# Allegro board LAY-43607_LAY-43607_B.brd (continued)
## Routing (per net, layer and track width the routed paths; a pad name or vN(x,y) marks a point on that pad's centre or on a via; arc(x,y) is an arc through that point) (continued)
CPU_RESET_REQ_B: length 88.3
  TOP w0.137: v3(71.83,49.39) 71.43,49 U14.F10 ; v2(127.13,40.21) 128.21,40.21 129.8,41.8 129.8,43.21 130.44,43.86 J14.2
  L3_INT_1 w0.107: v2(115.3,32.02) 114.5,32.82 114.5,43.92 105.39,53.03 104.4,53.03 102.57,54.86 96.08,54.86 95.16,53.95 87.37,53.95 86.43,54.88 84.48,54.88 82.15,52.56 82.15,51.11 v2(82.51,50.76)
  BOTTOM w0.137: v2(115.3,32.02) 122.99,32.02 127.13,36.16 v2(127.13,40.21) ; v2(82.51,50.76) 82.12,50.37 77.26,50.37 75.91,49.02 72.2,49.02 v3(71.83,49.39)
CPU_SPI_PCS0: length 58.9
  TOP w0.137: v2(63.18,72.87) 59.88,69.57 59.88,66.76 59.94,66.69 59.94,59.19 62.05,57.08 62.11,57.08 62.62,56.57 U14.U1 ; U36.6 82.29,96.74 82.27,96.73 v2(82.27,96.3)
  L3_INT_1 w0.107: v2(63.18,72.87) 63.18,73.28 63.23,73.34 63.23,74.39 65.37,76.53 69.63,76.53 70.25,77.15 72.84,77.15 73.98,78.29 73.98,86.81 75.27,88.1 75.27,89.51 79.63,93.87 79.63,94.02 79.35,94.3 79.35,94.45 79.5,94.6 79.65,94.6 79.93,94.32 80.08,94.32 80.23,94.47 80.23,94.62 79.95,94.9 79.95,95.05 80.1,95.2 80.26,95.2 80.53,94.93 80.68,94.93 81.77,96.01 81.98,96.01 v2(82.27,96.3)
  BOTTOM w0.137: R861.2 82.15,96.49 82.27,96.36 v2(82.27,96.3)
CPU_SPI_PCS1: length 58.7
  TOP w0.137: v2(82.98,96.37) 82.92,96.43 82.92,96.56 82.79,96.69 82.79,96.77 82.78,96.78 U36.7 ; v2(64.52,72.84) 64.52,71.47 63.71,70.66 63.71,69.34 63.57,69.21 63.57,59.08 64.58,58.07 64.58,54.96 U14.R3
  L3_INT_1 w0.107: v2(82.98,96.37) 82.98,95.33 82.37,94.72 82.22,94.72 82.06,94.88 81.91,94.88 81.76,94.73 81.76,94.58 81.92,94.42 81.92,94.27 78,90.35 78,82.49 74.76,79.26 74.76,78.49 71.78,75.5 68.67,75.5 68.14,76.03 65.32,76.03 63.54,74.26 63.54,73.24 63.95,72.84 v2(64.52,72.84)
  BOTTOM w0.137: v2(82.98,96.37) 83.09,96.49 R862.2
CPU_SPI_PCS2: length 60.6
  TOP w0.137: U540.7 85.78,96.8 85.95,96.63 85.95,96.45 v2(86.02,96.38) ; U14.T3 62.98,55.03 62.98,56.63 61.25,58.36 61.25,62.08 60.34,62.99 60.34,66.92 60.24,67.02 60.24,69.37 63.22,72.35 v2(64,72.35)
  L3_INT_1 w0.107: v2(64,72.35) 65.13,72.35 65.89,73.1 71.72,73.1 79.42,80.8 79.42,81.84 82.76,85.18 82.76,92.25 86.01,95.5 86.01,95.97 86.02,95.97 v2(86.02,96.38)
  BOTTOM w0.137: R860.2 86.22,96.66 86.02,96.47 v2(86.02,96.38)
CPU_SPI_PCS3: length 58.4
  TOP w0.137: U14.V1 61.82,56.2 v2(61.42,56.6) ; U540.6 85.28,96.61 85.31,96.58 v2(85.31,96.46)
  L3_INT_1 w0.107: v2(63.97,73.43) 65.38,73.43 65.9,73.95 70.74,73.95 75.15,78.36 75.15,79.2 80.2,84.25 80.2,91.14 83.21,94.15 83.21,94.33 83.09,94.44 83.09,94.62 83.22,94.75 83.39,94.75 83.51,94.63 83.69,94.63 83.81,94.75 83.81,94.93 83.7,95.05 83.7,95.22 83.82,95.35 84,95.35 84.11,95.23 84.29,95.23 84.89,95.84 84.89,96.05 v2(85.31,96.46)
  BOTTOM w0.137: v2(63.97,73.43) 63.67,73.13 63.67,72.74 60.16,69.22 60.16,64.11 61.34,62.93 61.34,61.93 61.82,61.44 61.82,57.39 61.42,56.99 v2(61.42,56.6) ; R859.2 85.19,96.59 v2(85.31,96.46)
CPU_SPI_SCK: length 58.9
  TOP w0.137: U14.U2 62.22,55.8 62.22,56.36 59.6,58.98 59.6,66.38 59.37,66.61 59.37,69.76 v2(62.37,72.76) ; U539.7 79.69,96.81 v2(79.41,96.54) 79.19,96.76 U539.6
  L3_INT_1 w0.107: v2(62.37,72.76) 62.37,73.97 65.25,76.84 67.1,76.84 72.25,81.98 72.25,82.59 72.99,83.34 72.99,90.12 76.72,93.85 76.72,94 76.23,94.49 76.23,94.64 76.38,94.8 76.53,94.8 77.02,94.3 77.18,94.3 77.33,94.45 77.33,94.6 76.83,95.1 76.83,95.25 76.98,95.4 77.13,95.4 77.63,94.91 77.78,94.91 77.93,95.06 77.93,95.21 77.44,95.7 77.44,95.85 77.59,96 77.74,96 78.23,95.51 78.38,95.51 v2(79.41,96.54)
CPU_SPI_SIN: length 55.1
  TOP w0.137: v2(62.22,55) U14.U3 ; v2(76.19,96.33) 76.19,96.76 76.19,96.76 U37.2
  L3_INT_1 w0.107: v2(76.19,96.33) 74.81,94.96 74.66,94.96 74.45,95.16 74.29,95.16 74.15,95.02 74.15,94.87 74.36,94.66 74.36,94.51 74.21,94.35 74.05,94.35 73.87,94.54 73.71,94.54 73.56,94.39 73.56,94.24 73.75,94.05 73.75,93.9 70.24,90.39 70.24,85.77 70.4,85.62 70.4,83.57 69.78,82.95 69.78,79.98 68.14,78.34 65.08,78.34 61.88,75.14 v2(61.88,73.77)
  BOTTOM w0.137: v2(61.88,73.77) 61.88,71.59 59.82,69.52 59.82,63.96 61,62.78 61,61.78 61.48,61.3 61.48,57.54 61.03,57.09 61.03,56.43 61.26,56.2 61.86,56.2 62.22,55.84 v2(62.22,55)
CPU_SPI_SOUT: length 56.5
  TOP w0.137: v2(61.42,55) U14.V3 ; U35.7 73.89,96.63 v2(73.65,96.38) 73.4,96.63 U35.6
  L3_INT_1 w0.107: v2(61.46,72.55) 61.46,75.21 61.48,75.23 61.5,75.23 64.92,78.65 68.01,78.65 69.42,80.06 69.42,85.22 69.51,85.31 69.51,86.58 67.91,88.19 67.91,90.65 71.9,94.64 71.9,94.79 71.64,95.05 71.64,95.2 71.79,95.35 71.95,95.35 72.2,95.09 72.35,95.09 72.51,95.25 72.51,95.4 72.25,95.66 72.25,95.81 72.4,95.96 72.55,95.96 72.81,95.7 72.96,95.7 v2(73.65,96.38)
  BOTTOM w0.137: v2(61.42,55) 61.03,55.39 61.03,56.07 60.78,56.33 60.78,57.19 61.02,57.44 61.02,57.56 61.14,57.68 61.14,61.16 60.66,61.64 60.66,62.64 59.48,63.82 59.48,69.66 61.46,71.64 v2(61.46,72.55)
CPU_SVDD: length 6
  TOP w0.381: U14.Y17 v1(59.82,43) ; v1(60.63,43.8) 61.02,44.2 U14.W16 ; U14.W10 v1(60.62,49.39) ; U14.W14 v1(60.63,46.19) ; U14.Y19 v1(59.82,41.4) ; U14.Y18 v1(59.82,42.2) ; U14.W13 v1(60.63,46.99) ; v1(60.63,44.6) 61.02,45 U14.W15
  BOTTOM w0.381: v1(60.62,49.39) 60.62,49.81 R260.2 ; v1(60.63,46.19) 60.79,46.03 R261.2
  vias: v4(44.82,39.26) v4(46.33,38.92) v4(47.37,38.93)
CPU_TBSCAN_EN_B: length 24.1
  TOP w0.137: v2(85.49,45.81) R177.1 R171.2 ; v3(71.02,41.4) U14.F19
  L3_INT_1 w0.107: v2(78.01,40.49) 77.92,40.58 73.24,40.58 72.87,40.95 72.56,40.95 72.18,41.33 72.18,41.54 71.97,41.75 71.38,41.75 v3(71.02,41.4)
  L4_INT_2 w0.107: v2(85.49,45.81) 85.79,46.11 85.79,46.51 85.05,47.25 80.78,47.25 80.29,46.76 80.29,42.77 v2(78.01,40.49)
CPU_TCK: length 146.7
  TOP w0.137: J15.4 v2(20.57,81.55) 19.85,81.55 19.35,82.05 15.75,82.05 R355.2 ; v3(72.62,42.2) U14.E18
  L3_INT_1 w0.107: v2(92.34,39.45) 91.28,40.51 88.41,40.51 87.5,41.42 86.7,41.42 86.3,41.82 83.94,41.82 82.22,43.54 80.27,43.54 80.23,43.59 74.52,43.59 74.37,43.44 73.36,43.44 73.07,43.14 73.07,42.64 v3(72.62,42.2) ; v2(20.57,81.55) 23.74,81.55 26.45,78.84 28.5,78.84 33.09,74.26 35.46,74.26 35.92,73.8 35.92,73.25 37.07,72.09 37.51,72.09 38.05,71.55 38.85,71.55 39.27,71.96 43.64,71.96 44.13,71.47 51.44,71.47 52.25,70.66 56.72,70.66 58.96,68.42 62.05,68.42 62.24,68.23 64.51,68.23 64.76,68.48 68.07,68.48 68.5,68.05 71.85,68.05 72.98,69.17 74.47,69.17 74.75,68.89 74.75,68.82 75,68.57 84.23,68.57 86.72,71.05 94.79,71.05 94.96,70.88 v2(95.37,70.88)
  L4_INT_2 w0.107: v2(95.37,70.88) 95.37,70.47 95.44,70.4 95.44,67.61 95.68,67.37 95.68,65.6 95.12,65.04 95.12,64.51 95.3,64.33 95.3,61.26 94.83,60.79 94.83,55.35 94.48,55 94.25,55 94.03,54.78 94.03,50.54 94.06,50.51 94.06,50.17 94.03,50.13 94.03,45.27 92.34,43.59 v2(92.34,39.45)
CPU_TDI: length 143.6
  TOP w0.137: J15.8 v2(20.6,84.09) ; v3(71.02,43) U14.G17
  L3_INT_1 w0.107: v2(95.7,71.8) 94.55,71.8 94.27,71.52 85.55,71.52 83.12,69.09 76.04,69.09 75.46,69.67 72.69,69.67 71.54,68.51 68.7,68.51 68.26,68.95 64.56,68.95 64.32,68.7 62.43,68.7 62.24,68.89 59.15,68.89 56.91,71.13 52.44,71.13 51.62,71.96 44.34,71.96 43.87,72.43 39.03,72.43 36.57,74.89 34.31,74.89 29.57,79.63 26.76,79.63 22.3,84.09 v2(20.6,84.09) ; v2(91.74,41.43) 90.93,41.43 90.09,42.27 88.15,42.27 87.5,42.92 85.09,42.92 84.91,43.11 83.8,43.11 82.29,44.62 82.29,45.15 81.77,45.68 81.4,45.68 80.95,46.13 80.59,46.13 79.45,44.98 72.96,44.98 72.66,44.69 72.66,44.69 72.15,44.18 71.6,44.18 71.48,44.06 71.46,44.06 71.46,43.44 v3(71.02,43)
  L4_INT_2 w0.107: v2(91.74,41.43) 91.74,43.49 93.24,44.99 93.24,55.07 92.68,55.63 92.68,57.75 92.61,57.82 92.61,58.32 93.01,58.72 93.01,61.66 93.16,61.8 93.16,64.04 92.72,64.48 92.72,66.47 92.98,66.73 93.01,66.73 95.17,68.88 95.17,70.34 94.96,70.55 94.96,71.05 95.03,71.12 95.03,71.14 v2(95.7,71.8)
CPU_TDO: length 136.6
  TOP w0.137: J15.6 v2(20.57,82.82) ; v3(72.62,40.6) U14.E20
  L3_INT_1 w0.107: v2(94.44,54.59) 93.83,54.59 93.66,54.43 88.78,54.43 87.57,55.64 84.21,55.64 v2(83.34,54.77) ; v2(95.96,71.22) 95.89,71.29 85.68,71.29 83.27,68.87 83.23,68.87 83.21,68.85 75.94,68.85 75.36,69.44 72.87,69.44 71.72,68.28 68.6,68.28 68.17,68.71 64.66,68.71 64.42,68.47 62.34,68.47 62.15,68.66 59.06,68.66 56.82,70.9 52.34,70.9 51.52,71.72 44.23,71.72 43.76,72.2 38.85,72.2 36.39,74.66 34.21,74.66 29.65,79.21 26.81,79.21 23.2,82.82 v2(20.57,82.82)
  L4_INT_2 w0.107: v2(95.96,71.22) 95.96,70.73 95.8,70.57 95.8,67.58 95.92,67.47 95.92,65.5 95.36,64.94 95.36,64.6 95.53,64.43 95.53,61.11 95.18,60.75 95.18,55.34 v2(94.44,54.59) ; v3(72.62,40.6) 77.38,40.6 80.05,43.27 80.05,46.85 80.4,47.2 80.4,49.12 82.1,50.82 82.1,50.92 82.12,50.94 82.12,53.55 v2(83.34,54.77)
CPU_TMS: length 133.3
  TOP w0.137: J15.2 v2(20.6,80.28) ; v3(71.02,42.2) U14.G18
  L3_INT_1 w0.107: v2(20.6,80.28) 22.41,80.28 22.85,79.84 23,79.84 23.67,80.51 23.82,80.51 23.97,80.36 23.97,80.21 23.3,79.54 23.3,79.39 23.45,79.24 23.6,79.24 24.27,79.91 24.42,79.91 24.57,79.76 24.57,79.61 23.9,78.94 23.9,78.79 24.05,78.64 24.21,78.64 24.87,79.31 25.02,79.31 25.17,79.16 25.17,79 24.51,78.34 24.51,78.19 24.66,78.03 24.81,78.03 25.48,78.7 25.63,78.7 25.78,78.55 25.78,78.4 25.11,77.73 25.11,77.58 25.28,77.42 26.78,77.42 27.52,78.16 27.7,78.16 27.82,78.03 27.82,77.85 27.25,77.28 27.25,77.11 27.37,76.98 27.55,76.98 28.12,77.55 28.3,77.55 28.42,77.43 28.42,77.25 27.85,76.68 27.85,76.5 28.35,76 30.31,76 30.48,75.83 30.48,75.68 29.64,74.84 29.64,74.69 29.79,74.54 29.94,74.54 30.78,75.38 30.93,75.38 31.08,75.23 31.08,75.08 30.24,74.24 30.24,74.09 30.39,73.94 30.54,73.94 31.38,74.78 31.53,74.78 31.69,74.63 31.69,74.48 30.84,73.64 30.84,73.48 30.99,73.33 31.15,73.33 31.99,74.18 32.14,74.18 32.29,74.02 32.29,73.87 31.45,73.03 31.45,72.88 31.6,72.73 31.75,72.73 32.59,73.57 32.74,73.57 34.89,71.42 37.51,71.42 37.94,71 39.04,71 39.54,71.5 43.17,71.5 43.72,70.95 51.3,70.95 52.05,70.2 56.52,70.2 58.94,67.78 v2(61.06,67.78)
  BOTTOM w0.137: v2(61.06,67.78) 61.36,68.08 63.86,68.08 64.54,67.4 64.54,66.08 64.81,65.82 65.7,65.82 65.83,65.95 65.83,67.92 66.14,68.23 66.14,68.62 65.65,69.11 60.93,69.11 60.5,68.68 60.5,67.73 60.75,67.48 60.76,67.48 60.76,66.82 60.92,66.66 63.44,66.66 63.6,66.5 63.6,66.27 63.44,66.11 60.92,66.11 60.76,65.95 60.76,65.72 60.92,65.56 63.44,65.56 63.6,65.4 63.6,65.17 63.44,65.01 60.92,65.01 60.76,64.85 60.76,63.98 61.68,63.07 61.68,62.07 62.16,61.58 62.16,59.91 63.69,58.39 63.69,55.99 64.24,55.44 64.24,50.71 64.23,50.7 64.23,41.22 64.45,41 69.55,41 69.85,41.29 69.85,41.55 70.1,41.8 70.51,41.8 70.91,42.2 v3(71.02,42.2)
CPU_TRST_B: length 76.3
  TOP w0.137: v2(116.57,17.03) 105.22,17.03 v2(103.46,18.79) ; U56.4 119.54,26.41 119.45,26.32 118.49,26.32 R305.2 v2(118.1,25.82) ; v3(71.82,41.4) U14.E19
  L3_INT_1 w0.107: v2(116.57,17.03) 117.08,17.54 117.08,19.99 117.05,20.02 117.05,25.11 117.76,25.82 v2(118.1,25.82) ; v3(71.82,41.4) 71.47,41.04 70.88,41.04 70.67,41.25 70.67,41.46 70.37,41.75 70.08,41.75 69.78,41.46 69.78,41.25 69.04,40.51 69.04,38.87 69.33,38.58 69.58,38.58 69.87,38.29 69.87,38.04 70.08,37.84 75.25,37.84 75.79,37.29 83.89,37.29 90.6,30.58 92.79,30.58 103.46,19.9 v2(103.46,18.79)
CPU_USB_HVDD: length 3
  TOP w0.381: U14.L8 67.82,50.99 v1(67.83,50.99) ; U14.K8 68.23,50.6 v1(68.63,50.99)
  BOTTOM w0.381: FL5.3 C159.1
  BOTTOM w0.508: C159.1 62.72,59.99 v4(62.8,59.91)
CPU_USB_SDVDD: length 3.1
  TOP w0.381: v1(67.03,50.99) 67.02,50.99 U14.M8 ; U14.M7 67.02,51.79 v1(67.03,51.79)
  BOTTOM w0.381: FL4.3 C155.1
  BOTTOM w0.508: v4(65.57,59.91) 65.26,60.22 C155.1
CPU_USB_SVDD: length 3.2
  TOP w0.381: U14.K7 68.23,51.4 v1(68.63,51.79) ; v1(67.83,51.79) 67.82,51.79 U14.L7
  BOTTOM w0.508: FL3.3 68.18,61.64 68.17,61.62 68.17,60.56 C151.1 68.13,59.74 v4(68.18,59.69)
CPU_VDD: length 59.8
  TOP w0.381: v1(68.62,42.2) 68.22,42.6 U14.K18 v1(67.82,43) U14.L17 v1(67.02,43.8) 66.62,44.2 U14.M16 v1(66.22,44.6) 65.82,45 U14.N15 ; v1(67.82,46.99) U14.L13 67.42,46.6 v1(67.02,46.19) U14.M14 ; U14.R11 v1(63.83,48.59) 63.42,49 U14.T10 v1(63.03,49.39) 62.62,49.8 U14.U9 v1(62.23,50.19) ; v1(60.62,48.59) U14.W11 61.02,48.19 v1(61.42,47.79) U14.V12 61.82,47.4 v1(62.22,46.99) U14.U13 v1(63.03,46.19) U14.T14 ; v1(65.42,41.39) U14.N19 v1(65.43,42.19) 65.02,42.6 U14.P18 ; v1(61.43,49.39) U14.V10 v1(62.22,48.59) U14.U11 62.62,48.2 v1(63.03,47.79) U14.T12 63.42,47.39 v1(63.82,46.99) U14.R13 ; v1(60.63,43) 61.02,43.4 U14.W17 v1(61.43,43.8) 61.82,44.2 U14.V16 61.82,44.2 v1(62.23,44.6) 62.62,45 U14.U15 ; U14.P14 v1(65.42,46.19) U14.N13 v1(66.22,46.99) U14.M12 v1(67.02,47.79) U14.L11 v1(67.82,48.59) ; U14.L15 v1(67.82,44.6) 67.87,44.55 U14.K16 68.22,44.2 v1(68.62,43.8) ; U14.K14 v1(68.62,46.19) ; U14.R9 v1(63.83,50.19) ; U14.V14 v1(61.42,46.19) ; v2(67.03,41.4) 67.42,41.8 U14.L19 v1(67.02,42.2) 66.62,42.6 U14.M18 v1(66.22,43) 65.82,43.4 U14.N17 v1(65.42,43.8) 65.02,44.2 U14.P16 ; U14.R19 64.22,41.79 v1(63.83,41.39) ; U14.K20 68.22,41 v1(67.83,40.6) ; v1(66.22,50.19) U14.N9 v1(65.42,49.39) U14.P10 ; U14.P12 v1(65.42,47.79) U14.N11 v1(66.22,48.59) U14.M10 v1(67.02,49.39) ; v1(60.62,41.4) U14.W19 61.02,41.8 v1(61.43,42.2) 61.82,42.6 U14.V18 61.82,42.6 v1(62.23,43) 62.62,43.4 U14.U17 62.62,43.4 v1(63.03,43.8) 63.42,44.2 U14.T16 v1(63.83,44.6) 64.22,45 U14.R15 ; U14.R17 64.22,43.4 v1(63.83,43) U14.T18 63.42,42.6 v1(63.03,42.2) 62.62,41.8 U14.U19 62.62,41.8 v1(62.23,41.4) 61.82,41 U14.V20 61.82,41 v1(61.43,40.6)
  TOP w0.508: C169.1 84.69,55.26 v5(84.69,54.35) ; C172.1 86.09,55.29 v5(86.09,54.4) ; C166.1 v5(89.59,35.3)
  L4_INT_2 w0.889: 40.3,38.16 J12.1 40.3,36.74
  BOTTOM w0.508: FL3.1 68.18,63.75 67.91,64.02 v4(67.91,64.03) ; 84.72,55.39 84.72,54.37 v5(84.69,54.35) ; v5(86.09,54.4) 86.27,54.58 86.27,55.39 ; FL4.1 v4(65.26,64.08) ; C166.1 v5(89.59,35.3)
  BOTTOM w0.889: 40.3,36.74 J12.1 40.3,38.16 ; 103.82,58.79 J9.2 ; J9.2 104.53,59.5 ; J9.2 103.11,59.5
  vias: v1(63.03,40.56) v4(42.28,40.78) v4(42.28,39.97) v4(42.28,39.13) v4(42.67,36.17) v4(42.81,38.29) v4(87.31,55.09) v4(87.32,52.91) v4(88.68,55.91) v4(88.98,52.85) v4(90.53,52.87) v4(91.2,53.02) v4(91.37,55.33) v4(91.88,52.82) v5(96.63,39.9) v5(96.63,38.5) v5(96.63,37.1) v5(96.63,35.7) v5(96.76,54.37) v5(96.76,52.98) v5(96.76,51.58) v5(96.76,50.18) v5(96.89,46.88) v5(96.89,45.48) v5(96.89,44.09) v5(96.89,42.69) v5(98.16,39.9) v5(98.16,38.5) v5(98.16,37.1) v5(98.16,35.7) v5(98.28,54.37) v5(98.28,52.98) v5(98.28,51.58) v5(98.28,50.18) v5(98.28,46.88) v5(98.28,45.48) v5(98.28,44.09) v5(98.28,42.69) v5(99.68,39.9) v5(99.68,38.5) v5(99.68,37.1) v5(99.68,35.7) v5(99.81,54.37) v5(99.81,52.98) v5(99.81,51.58) v5(99.81,50.18) v5(101.2,39.9) v5(101.2,38.5) v5(101.2,37.1) v5(101.2,35.7) v5(101.33,54.37) v5(101.33,52.98) v5(101.33,51.58) v5(101.33,50.18)
CPU_VDD_I:
  vias: v5(103.11,55.01) v5(103.11,53.61) v5(103.11,52.21) v5(103.11,50.94) v5(103.11,46.75) v5(103.11,45.36) v5(103.11,43.96) v5(103.11,42.56) v5(103.11,41.17) v5(103.11,39.77) v5(103.11,38.37) v5(103.11,36.97) v5(103.11,35.58) v5(103.11,34.05) v5(103.62,49.91) v5(104.25,56.79) v5(104.25,55.39) v5(104.25,53.99) v5(104.25,40.91) v5(104.63,36.14) v5(104.63,34.94) v5(105.27,56.79) v5(105.27,55.39) v5(105.27,53.99) v5(105.27,40.91) v5(105.65,36.14) v5(105.65,34.94) v5(105.65,33.55) v5(105.85,49.85) v5(106.28,56.79) v5(106.28,55.39) v5(106.28,53.99) v5(106.28,40.91) v5(106.67,36.11) v5(106.67,34.94) v5(106.61,33.85) v5(106.97,49.83) v5(107.05,43.07) v5(107.05,41.67) v5(107.3,54.75) v5(107.33,33.53) v5(107.81,46.75) v5(107.81,45.36) v5(107.81,43.96) v5(108.82,46.75) v5(108.82,45.36) v5(108.82,43.96) v5(109.84,46.75) v5(109.84,45.36) v5(109.84,43.96)
CPU_XVDD: length 2.8
  TOP w0.381: U14.AC7 v1(57.42,51.8) ; U14.AC9 v1(57.42,50.2) ; U14.AC14 v1(57.42,45.4) ; v1(57.42,47.8) U14.AC12 ; U14.AC20 v1(58.22,41.4)
  vias: v1(57.82,43.4) v4(44.99,45.91) v4(45.78,45.9) v4(48.19,52.81) v4(48.25,51.45) v4(49.15,52.86)
D1_ALERT_B: length 145.2
  TOP w0.137: v2(89.06,30.34) 89.04,30.37 89.04,30.95 88.9,31.09 87.8,31.09 87.67,30.95 87.67,29.71 87.5,29.55 87.28,29.55 87.12,29.71 87.12,30.18 86.96,30.34 86.73,30.34 86.57,30.18 86.57,29.71 86.41,29.55 86.18,29.55 86.02,29.71 86.02,30.18 85.86,30.34 85.63,30.34 85.47,30.18 85.47,29.71 85.31,29.55 85.08,29.55 84.92,29.71 84.92,30.18 84.76,30.34 84.5,30.34 83.02,31.83 74.21,31.83 73.48,32.55 73.47,32.55 U14.F28 ; R142.2 52.44,4.53 52.55,4.64 53.14,4.64 53.56,4.22 54.61,4.22 54.71,4.31 54.71,4.51 54.57,4.65 53.62,4.65 53.15,5.12 53.15,6.42 52.65,6.92 52.15,6.92 51.8,7.28 50.55,7.28 U18.P9 51.08,7.71 51.12,7.66 52.2,7.66 52.42,7.44 53.18,7.44 53.53,7.1 53.53,5.19 53.66,5.05 54.99,5.05 55.15,5.21 55.15,5.48 55.01,5.62 54.22,5.62 53.99,5.85 53.99,7.31 54.16,7.48 54.5,7.48 54.67,7.31 61.2,7.31 U17.P9 62,7.31 62.39,7.31 62.75,6.95 62.75,4.35 63.36,3.73 65.14,3.73 65.35,3.94 65.35,7.02 65.64,7.31 69.81,7.31 69.81,7.31 72.68,7.31 U565.P9 76.37,4.42 79.08,4.42 79.36,4.7 79.36,7.12 79.55,7.31 79.98,7.31 81.13,6.16 81.13,6.15 82,5.28 82.9,5.28 83.36,5.74 83.36,6.89 83.36,6.9 83.36,7.08 83.59,7.31 84.16,7.31 U16.P9 85.18,7.71 85.54,7.35 85.54,4.19 86,3.73 94.07,3.73 94.84,4.5 94.84,7.12 95.03,7.31 95.64,7.31 v1(96.04,7.71)
  L3_INT_1 w0.107: v2(89.06,30.34) 90.08,29.33 91.56,29.33 91.73,29.16 91.73,28.94 91.23,28.44 91.23,28.22 91.39,28.06 91.61,28.06 92.11,28.56 92.33,28.56 92.48,28.4 92.48,28.18 91.99,27.69 91.99,27.47 92.14,27.31 92.36,27.31 92.86,27.81 93.08,27.81 101.14,19.75 101.14,18.77 100.26,17.89 100.26,17.47 100.11,17.32 99.92,17.32 99.76,17.16 99.76,16.94 99.92,16.78 100.11,16.78 100.26,16.63 100.26,16.4 100.11,16.25 99.92,16.25 99.76,16.09 99.76,15.87 99.92,15.72 100.11,15.72 100.26,15.56 100.26,15.34 100.11,15.18 99.92,15.18 99.76,15.03 99.76,14.8 99.92,14.65 100.11,14.65 100.26,14.49 100.26,14.27 100.11,14.12 99.92,14.12 99.76,13.96 99.76,13.74 99.92,13.58 100.11,13.58 100.26,13.43 100.26,13.2 100.11,13.05 99.92,13.05 99.76,12.89 99.76,12.67 99.92,12.51 100.11,12.51 100.26,12.36 100.26,12.14 100.11,11.98 99.92,11.98 99.76,11.83 99.76,11.6 99.92,11.45 100.11,11.45 100.26,11.29 100.26,10.93 97.04,7.71 v1(96.04,7.71)
D1_MA0: length 134.8
  TOP w0.137: v1(45.32,7.71) 44.92,7.31 44.36,7.31 44.12,7.07 44.12,6.74 43.89,6.51 43.56,6.51 43.32,6.74 43.32,7.19 42.93,7.58 42.74,7.58 42.48,7.83 40.95,7.83 39.43,9.36 R111.1 ; U14.V27 61.46,35.03 61.46,34.45 61.71,34.2 61.71,29.62 66.35,24.99 74.65,24.99 75.33,25.67 v2(77.12,25.67)
  L3_INT_1 w0.107: v1(79.76,7.71) 79.38,8.09 78.1,8.09 78.07,8.12 78,8.12 77.78,8.35 77.78,8.46 77.54,8.7 77.39,8.7 77.37,8.67 77.22,8.67 77.06,8.82 77.06,8.97 77.09,9 77.09,9.15 76.93,9.32 76.39,9.32 76.28,9.21 76.28,8.81 76.18,8.71 75.96,8.71 75.86,8.81 75.86,9.21 75.75,9.32 75.54,9.32 75.43,9.21 75.43,8.81 75.32,8.71 75.11,8.71 75,8.81 75,9.21 74.9,9.32 74.68,9.32 74.58,9.21 74.58,8.81 74.47,8.71 74.26,8.71 74.15,8.81 74.15,9.21 74.04,9.32 73.62,9.32 73.24,9.69 72,9.69 71.9,9.58 71.9,9 71.79,8.89 71.2,8.89 71.1,8.78 71.1,8.23 70.99,8.12 70.61,8.12 70.5,8.23 70.5,8.49 70.39,8.59 70.18,8.59 70.07,8.49 70.07,8.23 69.97,8.12 69.25,8.12 69.04,7.9 68.48,7.9 v1(68.28,7.71) ; v2(77.12,25.67) 75.46,25.67 73.76,23.97 71.62,23.97 71.42,23.76 71.42,21.68 71.64,21.45 80.25,21.45 82.98,18.72 82.98,13.55 83.2,13.32 83.49,13.32 83.74,13.07 83.74,12.78 84.29,12.23 84.58,12.23 85.46,11.35 85.46,9.31 86.87,7.9 87.7,7.9 88.26,7.34 88.88,7.34 88.98,7.23 90.76,7.23 v1(91.24,7.71)
  L4_INT_2 w0.107: v1(56.8,7.71) 56.8,7.71 57.08,7.98 57.08,8.13 56.84,8.37 56.41,8.37 56.14,8.11 55,8.11 53.95,7.06 53.95,5.86 53.72,5.63 46.52,5.63 46.41,5.74 46.41,6.89 45.59,7.71 v1(45.32,7.71)
  BOTTOM w0.137: v1(91.24,7.71) 91.25,7.7 91.87,7.7 91.98,7.59 91.98,7.35 91.79,7.16 91.55,7.16 91.41,7.31 91.08,7.31 90.74,6.97 89.87,6.97 89.61,6.71 89.61,6.46 88.77,5.62 87.88,5.62 86.9,6.6 83.82,6.6 83.64,6.42 82.13,6.42 80.83,7.71 v1(79.76,7.71) ; v1(68.28,7.71) 67.99,7.42 67.99,7.18 67.88,7.07 67.88,6.74 68.11,6.51 68.11,6.22 67.97,6.08 67.22,6.08 66.82,5.68 64.27,5.68 64.05,5.89 64.05,6.45 62.4,8.11 61.29,8.11 60.81,7.63 60.24,7.63 59.77,8.11 58.77,8.11 58.37,7.71 v1(56.8,7.71)
D1_MA1: length 131.8
  TOP w0.137: v2(83.75,26.49) 83.11,26.49 81.93,27.67 70.57,27.67 65.94,32.3 65.94,33.71 66.25,34.03 66.25,34.97 U14.N27 ; v2(59.21,7.71) U17.P7
  L3_INT_1 w0.107: v2(83.75,26.49) 84.06,26.18 84.37,26.18 84.59,26.4 84.77,26.4 84.89,26.27 84.89,26.1 84.67,25.88 84.67,25.7 85.05,25.33 85.22,25.33 85.61,25.72 85.79,25.72 85.91,25.6 85.91,25.42 85.52,25.03 85.52,24.85 85.65,24.73 85.83,24.73 86.21,25.12 86.39,25.12 86.52,24.99 86.52,24.82 86.13,24.43 86.13,24.25 86.25,24.13 86.43,24.13 86.82,24.52 87,24.52 87.12,24.39 87.12,24.21 86.73,23.82 86.73,23.65 86.86,23.52 87.03,23.52 87.42,23.91 87.6,23.91 87.72,23.79 87.72,23.61 87.33,23.22 87.33,23.04 87.46,22.92 87.64,22.92 88.03,23.31 88.2,23.31 88.33,23.18 88.33,23.01 87.94,22.62 87.94,22.44 88.06,22.32 88.24,22.32 88.63,22.7 88.81,22.7 88.93,22.58 88.93,22.4 88.54,22.01 88.54,21.84 89.12,21.26 90.25,21.26 90.49,21.02 90.49,20.63 91.42,19.7 91.42,19.47 91.3,19.34 91.01,19.34 90.89,19.22 90.89,19.04 91.01,18.92 91.3,18.92 91.42,18.79 91.42,18.62 91.3,18.49 91.01,18.49 90.89,18.37 90.89,18.19 91.01,18.06 91.3,18.06 91.42,17.94 91.42,17.76 91.3,17.64 91.01,17.64 90.89,17.51 90.89,17.33 91.01,17.21 91.3,17.21 91.42,17.09 91.42,16.91 91.3,16.78 91.01,16.78 90.89,16.66 90.89,16.48 91.01,16.36 91.3,16.36 91.42,16.23 91.42,15.4 91.53,15.29 91.53,12.17 92.21,11.5 92.21,7.87 92.37,7.71 92.89,7.71 93,7.6 93,6.59 93.12,6.47 93.59,6.47 93.71,6.59 93.71,7.6 93.82,7.71 v1(94.44,7.71)
  L4_INT_2 w0.107: v1(94.44,7.71) 93.5,7.71 93.4,7.6 93.4,7.07 93.09,6.76 92.8,6.76 92.7,6.87 92.7,7.8 92.59,7.9 92.38,7.9 92.27,7.8 92.27,6.87 92.16,6.76 91.93,6.76 91.37,7.32 91.12,7.32 90.86,7.07 90.86,7.05 90.75,6.95 90.52,6.95 89.75,7.72 88.24,7.72 87.88,7.36 87.47,7.36 87.1,7.72 85.78,7.72 85.35,7.29 83.38,7.29 v1(82.96,7.71) 82.85,7.82 82.56,7.82 82.55,7.82 82.06,7.82 80.76,6.53 79.52,6.53 79.36,6.69 79.36,7.17 79.23,7.29 78.84,7.29 78.58,7.55 78.58,7.83 78.33,8.08 78.33,8.09 77.91,8.09 77.64,7.82 77.64,7.59 77.77,7.47 77.77,6.54 77.56,6.34 73.82,6.34 73.62,6.54 73.62,6.91 73.24,7.29 72.8,7.29 72.38,7.71 v1(71.48,7.71) 71.1,8.09 66.38,8.09 66.28,7.99 66.01,7.99 65.38,7.36 65.38,6.62 65.09,6.34 63,6.34 62.62,6.72 62.62,7.26 61.76,8.12 60.64,8.12 60.62,8.15 59.65,8.15 v2(59.21,7.71)
  BOTTOM w0.137: R113.1 49.65,4.47 49.65,4.66 49.3,5.02 49.09,5.02 48.77,4.7 48.58,4.7 48.39,4.89 48.39,5.08 48.7,5.39 48.7,5.62 48.51,5.81 48.31,5.81 47.89,5.38 47.7,5.38 47.49,5.59 47.49,5.94 47.94,6.38 47.94,7.57 48.07,7.71 v1(48.52,7.71) 48.92,7.31 51.61,7.31 52.45,6.48 52.45,6.13 53.64,4.94 56.21,4.94 56.69,5.41 56.69,5.69 56.92,5.93 57.2,5.93 57.63,6.35 57.63,6.54 57.4,6.77 57.4,6.96 57.59,7.16 57.79,7.16 58.21,6.74 58.58,6.74 59.21,7.37 v2(59.21,7.71)
D1_MA2: length 138.4
  TOP w0.137: U14.N28 65,33.77 65,33.14 65.39,32.75 65.39,32.22 66.61,31.01 70.45,27.17 73.45,27.17 v2(73.75,26.87) ; v1(56.8,6.91) 57.21,6.5 59.83,6.5 59.84,6.51 61.87,6.51 62.17,6.2 62.17,3.63 62.44,3.36 63.12,3.36 63.72,2.75 65.4,2.75 65.79,3.15 65.79,5.99 66.3,6.5 66.51,6.5 66.52,6.51 67.88,6.51 U565.R3 69.44,5.75 70.56,5.75 71.32,6.51 73.25,6.51 75.99,3.77 80.46,3.77 81.1,4.41 81.1,5.57 v1(79.76,6.91) ; v1(45.32,6.91) 45.32,6.67 44.92,6.27 44.92,5.86 44.92,5.86 44.92,5.74 44.2,5.02 44.16,5.02 44.14,5 43.74,5 43.72,4.97 42.3,4.97 42.16,4.83 41.49,4.83 41.19,5.13 41.19,5.61 40.96,5.84 40.63,5.84 39.91,6.56 R112.1
  L3_INT_1 w0.107: v1(91.24,6.91) 91.24,6.91 89.82,6.91 89.42,6.51 88.49,6.51 87.53,7.47 86.71,7.47 85.51,8.68 85.51,8.69 84.94,9.26 84.94,11.07 84.69,11.32 84.4,11.32 82.56,13.17 82.56,16.69 81.87,17.38 81.87,19.23 80.06,21.04 70.59,21.04 70.26,21.37 70.26,24.19 70.46,24.38 73.59,24.38 73.75,24.54 73.75,25.67 72.11,27.3 70.12,27.3 69.85,27.57 69.85,28.51 69.96,28.62 71.99,28.62 v2(73.75,26.87)
  L4_INT_2 w0.107: v1(56.8,6.91) 57.04,6.67 57.04,6.52 56.93,6.42 56.39,6.42 55.9,6.91 55.41,6.91 55.14,6.64 55.14,5.51 54.41,4.78 46.35,4.78 45.95,5.18 45.95,6.67 45.71,6.91 v1(45.32,6.91)
  BOTTOM w0.137: v1(91.24,6.91) 91.73,6.91 91.83,6.81 91.83,6.61 91.73,6.51 90.84,6.51 89.94,5.61 89.94,4.83 89.66,4.55 83.64,4.55 83.07,5.12 83.04,5.12 82.61,5.54 81.44,5.54 80.51,6.48 80.29,6.48 79.86,6.91 v1(79.76,6.91)
D1_MA3: length 141.1
  TOP w0.137: R115.1 48.37,4.77 48.23,4.91 47.42,4.91 47,5.33 47,9.13 47.4,9.53 47.66,9.53 48.52,8.67 U18.N7 48.92,8.91 51.47,8.91 52.35,9.79 52.35,10.98 52.03,11.3 52.03,12.29 52.29,12.55 53.74,12.55 54.02,12.28 54.02,11.54 54.74,10.82 54.74,9.14 54.97,8.91 56.97,8.91 57.07,9.01 58.68,9.01 59.18,8.51 U17.N7 60.4,8.91 62.36,8.91 63.63,7.64 63.63,5.33 63.8,5.16 64.33,5.16 64.46,5.29 64.46,7.38 65.08,8 65.08,8.08 65.08,8.08 65.08,8.57 65.75,9.24 66.19,9.24 66.52,8.91 71.08,8.91 v1(71.48,8.51) 71.88,8.91 73.25,8.91 73.4,9.07 73.76,9.07 74.13,8.7 74.13,8.23 76.87,5.48 77.01,5.48 77.34,5.81 77.34,6 76.15,7.19 76.15,7.39 76.31,7.54 77.33,7.54 77.76,7.97 77.76,8.68 77.99,8.91 80.66,8.91 81.06,8.51 v1(82.96,8.51) ; U14.M28 66.62,34.22 66.52,34.12 66.52,32.35 70.69,28.18 76.41,28.18 77.03,28.8 81.83,28.8 83.44,27.19 84.65,27.19 v2(85.25,26.59)
  L3_INT_1 w0.107: v1(94.44,8.51) 92.88,8.51 92.75,8.63 92.75,12.7 92.03,13.43 92.03,15.31 92.25,15.53 arc(92.28,15.57) 92.29,15.63 92.29,19.8 87.74,24.36 87.74,26.09 88.4,26.75 88.4,28.65 88.28,28.77 87.46,28.77 87.33,28.65 87.33,26.43 87.21,26.3 87.03,26.3 86.91,26.43 86.91,28.65 86.78,28.77 86.6,28.77 86.48,28.65 86.48,26.43 86.35,26.3 86.18,26.3 86.05,26.43 86.05,28.65 85.93,28.77 85.44,28.77 85.25,28.59 v2(85.25,26.59)
  L4_INT_2 w0.107: v1(94.44,8.51) 94.05,8.9 93.33,8.9 93.23,8.79 93.23,8.27 93.12,8.16 92.91,8.16 92.8,8.27 92.8,8.79 92.69,8.9 92.38,8.9 91.58,8.1 91.04,8.1 90.85,8.3 90.85,8.64 90.57,8.92 87.36,8.92 87.14,9.14 86.27,9.14 85.83,9.59 85.61,9.59 85.51,9.48 85.51,8.38 85.28,8.15 84.58,8.15 84.36,7.93 83.8,7.93 83.22,8.51 v1(82.96,8.51)
D1_MA4: length 139.8
  TOP w0.137: v1(79.76,8.51) 80.58,8.51 80.98,8.11 82.51,8.11 85.75,8.11 86.41,7.45 86.41,5.3 86.75,4.96 90.61,4.96 90.61,4.97 91.14,4.97 91.81,5.63 91.81,7.94 v1(91.24,8.51) ; v2(76.24,28.93) 75.94,28.63 70.86,28.63 67.54,31.95 67.54,34.11 67.42,34.22 U14.L28 ; R114.1 39.88,11.62 40.17,11.33 40.17,9.91 40.64,9.43 42.13,9.43 43.46,8.11 44.77,8.11 44.92,8.26 44.92,8.35 45.08,8.51 v1(45.32,8.51) ; U17.N3 v2(57.52,8.51)
  L3_INT_1 w0.107: v2(57.52,8.51) 58.2,8.51 58.59,8.12 58.59,6.76 58.83,6.53 59.19,6.53 59.3,6.42 59.3,6.15 59.41,6.05 59.62,6.05 59.73,6.15 59.73,6.42 59.83,6.53 62.08,6.53 62.19,6.42 62.19,6.18 62.3,6.07 62.51,6.07 62.62,6.18 62.62,6.42 62.72,6.53 63.85,6.53 64.19,6.87 64.19,8.8 65.12,9.72 66.81,9.72 67.06,9.47 67.06,9.18 67.35,8.9 67.35,8.89 67.64,8.89 68.02,8.51 v1(68.28,8.51) 68.78,8.51 70.27,10 70.27,11.13 70.46,11.32 70.7,11.32 70.8,11.43 70.8,11.69 70.91,11.79 71.12,11.79 71.23,11.69 71.23,11.43 71.34,11.32 71.55,11.32 71.66,11.43 71.66,11.69 71.76,11.79 71.98,11.79 72.08,11.69 72.08,11.43 72.19,11.32 73.46,11.32 73.57,11.43 73.57,11.57 73.68,11.67 73.89,11.67 74,11.57 74,11.43 74.1,11.32 74.32,11.32 74.42,11.43 74.42,11.57 74.53,11.67 74.74,11.67 74.85,11.57 74.85,11.43 74.96,11.32 75.17,11.32 75.28,11.43 75.28,11.57 75.38,11.67 75.6,11.67 75.7,11.57 75.7,11.43 75.81,11.32 75.97,11.32 76.45,10.85 76.92,10.85 77.58,10.19 77.58,9.83 77.68,9.72 78.36,9.72 78.57,9.51 78.57,9.11 78.78,8.91 79.36,8.91 v1(79.76,8.51) ; v1(91.24,8.51) 90.84,8.11 90.28,8.11 90.27,8.1 89.94,7.78 89.34,7.78 88.86,8.26 88.64,8.26 88.18,8.72 87.47,8.72 86.88,9.32 86.88,9.71 86.9,9.74 86.9,10.94 85.58,12.26 85.58,12.86 85.15,13.29 84.84,13.29 84.58,13.55 84.58,18.7 84.25,19.03 84.23,19.03 80.98,22.28 72.69,22.28 72.5,22.46 72.5,23.01 72.64,23.15 75.89,23.15 75.93,23.18 75.98,23.18 78.03,25.22 78.03,26.14 77.11,27.06 75.72,27.06 75.43,27.35 75.43,32.36 75.53,32.47 76.13,32.47 76.24,32.36 v2(76.24,28.93)
  L4_INT_2 w0.107: v2(57.52,8.51) 57.37,8.65 56.45,8.65 56.2,8.91 55.74,8.91 55.48,8.64 54.69,8.64 54.41,8.92 53.69,8.92 53.12,8.36 53.12,7.05 52.78,6.7 52.04,6.7 51.44,7.31 46.94,7.31 45.74,8.51 v1(45.32,8.51)
D1_MA5: length 140.1
  TOP w0.137: R117.1 49.26,4.24 48.92,4.58 48.92,5.07 48.78,5.21 47.98,5.21 47.33,5.86 47.33,8.78 47.48,8.93 47.84,8.93 48,8.77 48,8.38 48.27,8.11 48.35,8.11 48.36,8.11 48.92,8.11 U18.P8 49.72,8.11 51.53,8.11 51.87,8.45 52.04,8.45 52.61,7.88 52.8,7.88 53.16,8.25 53.16,8.44 52.71,8.9 52.71,9.28 52.94,9.52 52.94,10.12 53.08,10.26 54.1,10.26 54.3,10.06 54.3,9.45 53.61,8.76 53.61,8.11 53.8,7.92 54.64,7.92 54.83,8.11 56.97,8.11 57.36,7.72 58.45,7.72 58.83,8.11 60.17,8.11 60.57,7.71 U17.P8 61.2,8.11 61.44,8.11 62.42,8.11 63.19,7.34 63.19,4.59 63.47,4.31 64.68,4.31 64.91,4.54 64.91,7.2 65.46,7.75 66.16,7.75 66.52,8.11 71.88,8.11 U565.P8 72.68,8.11 73.25,8.11 73.31,8.04 73.69,8.04 76.88,4.86 77.19,4.86 77.32,4.99 77.32,5.17 77.46,5.3 77.73,5.3 77.87,5.17 77.87,4.99 78.01,4.86 78.29,4.86 78.57,5.14 78.57,5.94 78.56,5.94 78.56,7.93 78.73,8.11 80.02,8.11 80.16,7.97 80.16,7.58 80.52,7.22 80.81,7.22 80.95,7.35 80.95,7.63 81.09,7.77 81.36,7.77 81.5,7.63 81.5,7.35 81.63,7.22 v2(82.3,7.22) 82.81,7.31 83.13,7.31 83.34,7.52 U16.P8 ; U14.L27 67.86,34.96 67.86,33.84 67.98,33.73 67.98,32.14 70.77,29.34 74.66,29.34 74.83,29.17 75.2,29.17 75.39,29.35 81.9,29.35 83.45,27.8 87.58,27.8 88.14,27.25 90.28,27.25 90.44,27.09 90.44,25.61 90.6,25.45 90.83,25.45 90.99,25.61 90.99,27.09 91.15,27.25 v2(91.58,27.25)
  L3_INT_1 w0.107: v2(91.58,27.25) 91.58,26.71 91.77,26.51 92.13,26.51 92.26,26.38 92.26,26.02 92.38,25.89 92.56,25.89 92.68,26.02 92.68,26.38 92.81,26.51 93.71,26.51 93.88,26.34 93.88,26.17 93.58,25.87 93.58,25.72 93.74,25.57 93.89,25.57 94.18,25.87 94.36,25.87 99.35,20.87 99.35,10.69 98.87,10.21 98.7,10.21 98.53,10.38 98.35,10.38 98.22,10.25 98.22,10.08 98.39,9.91 98.39,9.73 98.27,9.61 98.09,9.61 97.92,9.78 97.74,9.78 97.62,9.65 97.62,9.47 97.79,9.3 97.79,9.13 97.67,9 97.49,9 97.32,9.17 97.14,9.17 97.02,9.05 97.02,8.87 97.19,8.7 97.19,8.52 96.79,8.12 95.66,8.12 v1(95.24,7.71)
  L4_INT_2 w0.107: v1(95.24,7.71) 94.86,7.32 94.34,7.32 94.31,7.29 94.28,7.29 93.48,6.49 90.6,6.49 90.2,6.89 89.32,6.89 88.93,7.28 88.52,7.28 88.51,7.28 88.38,7.28 88.05,6.95 87.29,6.95 87.1,7.14 85.5,7.14 85.44,7.07 83.28,7.07 83.22,7.14 82.76,7.14 82.68,7.22 v2(82.3,7.22)
D1_MA6: length 135.3
  TOP w0.137: U14.K28 68.22,33.93 68.47,33.68 68.47,32.27 70.95,29.79 74.84,29.79 v2(75.02,29.61) ; v1(44.52,7.71) 44.29,7.71 43.89,7.31 43.56,7.31 43.32,7.54 43.32,7.62 41.95,8.99 41.68,8.99 41.55,8.85 41.55,8.41 41.41,8.28 41.14,8.28 41,8.41 41,8.85 40.86,8.99 40.46,8.99 39.72,9.73 39.72,10.29 39.59,10.43 R116.1
  L3_INT_1 w0.107: v1(78.96,7.71) 77.78,6.52 77.78,5.55 77.56,5.33 77.12,5.33 77.01,5.44 77.01,5.69 76.91,5.8 76.69,5.8 76.59,5.69 76.59,5.44 76.48,5.33 76.27,5.33 76.16,5.44 76.16,5.69 76.05,5.8 75.84,5.8 75.73,5.69 75.73,5.44 75.63,5.33 75.41,5.33 75.31,5.44 75.31,5.69 75.2,5.8 74.99,5.8 74.88,5.69 74.88,5.44 74.77,5.33 74.54,5.33 74.02,5.85 73.69,5.85 73.43,5.6 72.74,5.6 70.81,7.53 69.65,7.53 68.53,6.4 68.02,6.4 67.9,6.53 67.9,7.03 67.48,7.45 v1(67.48,7.71) ; v2(75.02,29.61) 74.63,29.99 74.63,33.39 74.52,33.5 73.5,33.5 73.39,33.39 73.39,27.92 74.76,26.55 77.04,26.55 77.61,25.97 77.61,25.45 75.72,23.56 72.43,23.56 72.09,23.21 72.09,22.1 72.33,21.87 80.63,21.87 83.78,18.71 83.78,13.55 84,13.32 84.29,13.32 84.54,13.07 84.54,12.72 85.84,11.42 85.84,9.51 87.04,8.31 87.87,8.31 88.43,7.75 88.93,7.75 89.17,7.5 90.24,7.5 v1(90.44,7.71)
  L4_INT_2 w0.107: v1(67.48,7.71) 67.48,7.53 67.27,7.32 66.4,7.32 66.22,7.14 66.22,6.74 66.01,6.54 66.01,5.99 65.71,5.69 62.83,5.69 62.4,6.12 62.4,6.87 61.97,7.29 61.44,7.29 61.05,7.68 60.63,7.68 60.24,7.29 59.84,7.29 59.62,7.07 59.62,6.67 59.51,6.56 57.44,6.56 57.26,6.74 57.26,7 56.96,7.29 56.66,7.29 56.25,7.71 v1(56,7.71) 56,7.23 55.9,7.13 55.32,7.13 54.85,6.66 54.85,5.8 54.27,5.22 46.51,5.22 46.17,5.56 46.17,6.76 45.63,7.3 44.31,7.3 44.2,7.41 44.2,7.6 44.31,7.71 v1(44.52,7.71)
  BOTTOM w0.137: v1(78.96,7.71) 78.56,8.11 78.56,8.72 78.75,8.91 79.13,8.91 79.36,8.67 79.36,8.34 79.6,8.11 80.85,8.11 82.14,6.82 83.27,6.82 83.7,7.25 88.33,7.25 88.39,7.31 88.4,7.31 88.41,7.32 88.85,7.32 88.99,7.46 88.99,7.63 89.17,7.81 89.4,7.81 89.54,7.67 89.54,7.46 89.67,7.32 90.05,7.32 v1(90.44,7.71)
D1_MA7: length 134.4
  TOP w0.137: U18.R8 v1(49.32,6.91) 49.72,6.51 49.72,5.46 49.91,5.27 50.5,5.27 50.73,5.49 50.73,6.7 50.86,6.84 51.61,6.84 52.14,6.31 52.14,5.88 50.79,4.53 50.79,4.33 R119.1 ; v1(95.24,6.91) 95.24,6.89 95.64,6.49 95.64,4.24 94.15,2.75 86.06,2.75 84.21,4.6 v2(84.21,5.5) 84.16,5.55 84.16,5.56 84.16,5.56 84.16,6.51 U16.R8 ; v2(93.3,28.31) 92.95,28.66 92.08,28.66 91.91,28.5 91.91,27.88 91.75,27.72 91.53,27.72 91.37,27.88 91.37,28.5 91.21,28.66 90.98,28.66 90.82,28.5 90.82,27.88 90.66,27.72 90.43,27.72 90.27,27.88 90.27,28.5 90.11,28.66 89.88,28.66 89.72,28.5 89.72,27.88 89.56,27.72 89.33,27.72 89.17,27.88 89.17,28.5 89.01,28.66 88.51,28.66 88.35,28.5 88.35,28.48 88.19,28.32 87.97,28.32 87.8,28.48 87.8,28.5 87.64,28.66 83.56,28.66 83.42,28.8 81.72,30.5 73.57,30.5 73.28,30.78 71.46,30.78 69.36,32.89 69.36,34.42 69.38,34.45 69.38,34.74 69.29,34.84 69.29,35.13 U14.J27
  L3_INT_1 w0.107: v1(95.24,6.91) 95.22,6.89 94.95,6.89 94.81,7.04 94.81,7.2 94.92,7.31 97.51,7.31 100.89,10.69 100.89,17.94 101.55,18.6 101.55,20.06 v2(93.3,28.31)
  L4_INT_2 w0.107: v2(84.21,5.5) 82.37,5.5 81.34,4.46 75.28,4.46 75.17,4.57 75.17,4.59 75.06,4.69 74.85,4.69 74.74,4.59 74.74,4.57 74.64,4.46 74.06,4.46 72.66,5.86 72.66,6.52 v1(72.28,6.91) 72.14,6.91 70.54,5.3 70.34,5.3 70.23,5.2 70.23,4.86 70.13,4.76 69.91,4.76 69.81,4.86 69.81,5.2 69.7,5.3 69.49,5.3 69.38,5.2 69.38,4.86 69.27,4.76 69.06,4.76 68.95,4.86 68.95,5.2 68.85,5.3 68.53,5.3 68.38,5.46 66.61,5.46 66.02,4.86 62.61,4.86 62.37,5.1 62.37,5.36 62.27,5.46 61.58,5.46 61.22,5.82 61.22,6.23 60.8,6.65 v1(60.8,6.91)
  BOTTOM w0.137: v1(60.8,6.91) 60.37,7.34 59.87,7.34 59.09,6.56 59.09,6.36 59.23,6.22 59.23,6.03 59.04,5.83 58.84,5.83 58.7,5.98 58.51,5.98 58.31,5.78 58.31,5.59 58.46,5.44 58.46,5.25 58.26,5.06 58.07,5.06 57.92,5.2 57.73,5.2 57.02,4.49 53.46,4.49 52,5.95 52,5.98 52,5.98 52,6.25 51.7,6.55 50.33,6.55 50.29,6.51 49.96,6.51 49.71,6.76 49.47,6.76 v1(49.32,6.91)
D1_MA8: length 134.3
  TOP w0.137: v1(44.52,6.91) 44.52,6.67 44.12,6.27 44.12,6.08 44.12,6.08 44.12,5.94 43.89,5.71 43.56,5.71 43.32,5.94 43.32,6.29 42.3,7.32 41.91,7.32 41.77,7.18 41.77,6.86 41.63,6.72 41.36,6.72 41.22,6.86 41.22,7.18 41.08,7.32 40.82,7.32 39.72,8.42 R118.1 ; U17.R2 56,6.91 v2(55.6,6.51) ; U15.R2 90.04,6.51 v2(90.04,6.51) ; U14.J28 69.02,34.22 68.92,34.11 68.92,32.45 71.1,30.27 v2(72.98,30.27)
  L3_INT_1 w0.107: v1(67.48,6.91) 67.48,6.25 67.63,6.1 68.76,6.1 69.81,7.14 70.56,7.14 73.25,4.46 74.23,4.46 74.33,4.56 74.33,4.79 74.44,4.89 74.65,4.89 74.76,4.79 74.76,4.56 74.87,4.46 75.08,4.46 75.19,4.56 75.19,4.79 75.29,4.89 75.51,4.89 75.61,4.79 75.61,4.56 75.72,4.46 75.93,4.46 76.04,4.56 76.04,4.79 76.15,4.89 76.36,4.89 76.47,4.79 76.47,4.56 76.57,4.46 78.24,4.46 78.57,4.78 78.57,6.51 v1(78.96,6.91) ; v2(90.04,6.51) 89.34,5.81 87.9,5.81 86.84,6.87 86.23,6.87 84.72,8.37 84.72,8.54 84.14,9.11 84.14,11.09 82.18,13.05 82.18,16.4 81.46,17.11 81.46,19.06 79.89,20.63 70.25,20.63 69.85,21.03 69.85,24.51 70.13,24.79 73.15,24.79 73.26,24.9 73.26,25.55 73.22,25.59 73.22,25.61 72.98,25.85 72.95,25.86 71.92,26.89 69.83,26.89 69.44,27.28 69.44,32.74 69.8,33.1 71.56,33.1 71.88,32.78 71.88,30.43 72.05,30.27 v2(72.98,30.27)
  L4_INT_2 w0.107: v1(44.52,6.91) 44.36,6.91 44.25,6.8 44.25,6.6 44.36,6.49 45.48,6.49 45.73,6.24 45.73,4.73 46.09,4.37 54.59,4.37 55.36,5.15 55.36,5.58 55.6,5.82 v2(55.6,6.51) 55.89,6.51 56.2,6.2 60.19,6.2 60.42,6.42 60.42,7.15 60.56,7.29 60.96,7.29 61.18,7.07 61.18,6.78 61.48,6.49 61.76,6.49 61.98,6.27 61.98,6.06 62.76,5.28 65.85,5.28 66.3,5.73 66.3,6.27 66.52,6.49 67.07,6.49 v1(67.48,6.91)
  BOTTOM w0.137: v1(78.96,6.91) 78.84,6.79 78.35,6.79 78.25,6.88 78.25,7.21 78.35,7.31 80.03,7.31 81.54,5.79 83.14,5.79 83.95,4.99 88.7,4.99 90.03,6.32 90.03,6.5 v2(90.04,6.51)
D1_MA9: length 130.5
  TOP w0.137: U16.R7 v2(81.38,6.57) ; v2(92.72,29.1) 92.71,29.11 92.21,29.11 92.05,29.27 92.05,30.62 91.89,30.78 91.66,30.78 91.5,30.62 91.5,29.27 91.34,29.11 91.12,29.11 90.95,29.27 90.95,30.62 90.79,30.78 90.57,30.78 90.41,30.62 90.41,29.27 90.25,29.11 83.74,29.11 81.9,30.94 73.75,30.94 73.47,31.22 73.47,31.22 73.02,31.67 72.4,31.67 71.01,33.06 71.01,33.96 70.62,34.35 U14.G28 ; v2(69.9,6.57) 70.24,6.91 U565.R7
  L3_INT_1 w0.107: v2(92.72,29.1) 93.36,29.1 101.96,20.49 101.96,18.43 101.3,17.76 101.3,10.52 97.3,6.51 96.56,6.51 96.55,6.51 94.84,6.51 v1(94.44,6.91) ; v2(81.38,6.57) 79.98,6.57 79.6,6.19 79.6,4.89 78.74,4.03 72.82,4.03 70.28,6.57 v2(69.9,6.57)
  L4_INT_2 w0.107: v1(94.44,6.91) 93.26,5.72 91.08,5.72 91.06,5.74 87.91,5.74 86.94,6.71 83.2,6.71 83.06,6.57 v2(81.38,6.57)
  BOTTOM w0.137: v2(69.9,6.57) 69.62,6.28 69.62,6.05 68.86,5.29 67.47,5.29 67.34,5.43 66.71,5.43 65.94,4.66 63.95,4.66 63.58,5.02 63.58,6.29 62.57,7.31 61.44,7.31 61.2,7.07 61.2,6.74 61.21,6.73 60.98,6.51 60.4,6.51 v1(60,6.91) 60,6.24 56.95,3.2 56.15,3.2 55.9,3.44 55.9,3.75 55.73,3.91 53.35,3.91 51.57,5.69 51.3,5.69 51.27,5.71 49.96,5.71 49.72,5.94 49.72,6.39 49.6,6.51 49.11,6.51 49.11,6.51 48.92,6.51 v1(48.52,6.91) 48.52,6.26 49.47,5.31 49.63,5.31 50.14,4.81 51.21,4.81 51.98,4.03 51.98,3.87 51.84,3.73 51.6,3.73 51.25,4.08 R121.1
D1_MA10: length 137.4
  TOP w0.137: U14.Y28 60.22,29.86 66.08,24.01 75.23,24.01 75.31,24.1 75.32,24.1 75.93,24.71 81.87,24.71 v2(82.43,24.15)
  L3_INT_1 w0.107: v1(79.76,9.31) 79.35,9.72 79.35,10.38 79.24,10.49 78.8,10.49 78.55,10.74 78.55,10.95 78.55,12.26 78.42,12.39 77.74,12.39 77.21,12.92 76.62,12.92 76.47,12.77 76.11,12.77 75.95,12.92 75.09,12.92 74.87,12.7 74.68,12.7 74.54,12.84 73.96,12.84 73.64,12.52 71.72,12.52 71.49,12.76 71.26,12.76 71.1,12.92 69.7,12.92 69.57,12.78 69.54,12.78 69.45,12.7 69.45,10.48 68.55,9.58 68.55,9.58 v1(68.28,9.31) 67.86,9.72 67.86,10.27 67.61,10.52 67.32,10.52 67.06,10.78 67.06,11.07 66.38,11.75 63.36,11.75 62.89,11.28 62.89,9.05 62.57,8.72 61.93,8.72 61.76,8.89 61.44,8.89 61.22,8.67 61.22,8.4 61.18,8.37 61.18,8.35 60.96,8.12 60.64,8.12 60.42,8.35 60.42,8.37 60.39,8.4 60.39,9.55 60.21,9.72 57.6,9.72 57.18,9.31 v1(56.8,9.31) ; v1(91.24,9.31) 90.86,9.69 89.44,9.69 88.66,10.48 88.66,11.77 88.15,12.28 87.33,12.28 86.75,12.86 86.75,14.57 86.31,15 86.31,15.34 86.51,15.53 86.51,19.81 82.75,23.57 82.14,23.57 81.95,23.76 81.95,24.12 81.69,24.38 81.69,24.4 79.95,26.14 79.95,27.13 79.05,28.03 78.52,28.03 78.41,28.14 78.41,28.33 78.52,28.44 79.12,28.44 80.32,27.25 80.32,26.26 v2(82.43,24.15)
  L4_INT_2 w0.107: v1(91.24,9.31) 91.74,9.8 92.21,9.8 92.32,9.91 92.32,10.38 92.21,10.49 89.08,10.49 88.74,10.15 88.07,10.15 87.61,10.61 85.07,10.61 84.94,10.48 84.94,9.95 84.72,9.72 84.19,9.72 84.18,9.72 82.17,9.72 82.17,9.72 80.18,9.72 v1(79.76,9.31) ; v1(56.8,9.31) 56.65,9.15 56.49,9.15 56.39,9.26 56.39,9.48 56.16,9.71 54.61,9.71 54.57,9.75 52.86,9.75 52.3,9.19 52.3,8.01 52.19,7.9 52.01,7.9 51.77,8.13 50.65,8.13 50.5,8.28 50.5,8.67 50.28,8.89 48.36,8.89 48.1,8.63 48.1,8.16 47.73,7.8 47.26,7.8 46.92,8.13 46.92,8.79 46.41,9.31 v1(45.32,9.31)
  BOTTOM w0.137: v1(45.32,9.31) 45,9.81 arc(44.94,9.94) 44.92,10.08 44.92,11.08 44.69,11.31 42.48,11.31 42.34,11.17 39.57,11.17 R120.1
D1_MA11: length 132.2
  TOP w0.137: U15.T2 v2(90.44,5.36) ; U565.T2 67.44,6.07 67.44,5.68 67.44,5.3 v2(67.17,5.03) ; U14.H28 69.8,34.57 69.8,33.07 71.65,31.22 v2(72.64,31.22) ; v1(44.52,6.11) 44.52,5.7 44.09,5.27 43.57,5.27 42.56,6.28 42.32,6.28 42.19,6.14 42.19,5.48 42.05,5.35 41.77,5.35 41.64,5.48 41.64,6.08 41.44,6.28 41.17,6.28 41.17,6.28 41.06,6.28 39.87,7.48 R123.1 ; v1(78.96,6.11) U16.T2 ; U17.T2 v2(56.23,5.59)
  L3_INT_1 w0.107: v2(56.23,5.59) 56.23,4.37 57.33,3.27 65.33,3.27 65.8,3.74 66.28,3.74 66.38,3.85 66.38,4.22 66.5,4.34 66.69,4.34 66.81,4.22 66.81,3.85 66.92,3.74 67.63,3.74 67.79,3.9 67.79,4.41 v2(67.17,5.03) ; v2(90.44,5.36) 91.6,5.36 91.7,5.25 91.7,4.61 91.6,4.51 86.81,4.51 84.53,6.79 82.03,6.79 80.95,7.88 80.95,10.81 79.8,11.96 79.8,17.81 77.97,19.64 69.95,19.64 69.03,20.57 69.03,34.19 69.14,34.29 72.54,34.29 72.64,34.19 v2(72.64,31.22)
  L4_INT_2 w0.107: v1(44.52,6.11) 44.52,4.78 45.75,3.55 55.55,3.55 56.23,4.22 v2(56.23,5.59)
  BOTTOM w0.137: v2(90.44,5.36) 90.89,5.36 91.09,5.16 91.09,4.64 90.56,4.1 82.78,4.1 81.72,5.17 81.3,5.17 80.36,6.11 v1(78.96,6.11) 78.29,5.44 76.84,5.44 74.96,7.31 71.95,7.31 69.94,5.3 69.22,5.3 68.74,4.82 67.38,4.82 v2(67.17,5.03)
D1_MA12: length 141.2
  TOP w0.137: R122.1 47.48,4.51 47.38,4.61 46.95,4.61 46.68,4.89 46.68,9.23 47.47,10.03 48.04,10.03 48.23,9.83 48.23,9.6 U18.M7 48.92,9.71 50.65,9.71 50.73,9.63 51.12,9.63 51.36,9.88 51.36,12.38 51.69,12.72 51.69,13.21 52.11,13.63 53.65,13.63 54.4,12.87 54.4,12.46 54.75,12.11 55.36,12.11 55.6,11.87 55.6,9.89 55.79,9.71 58.75,9.71 59.15,9.31 U17.M7 60.4,9.71 61.03,9.71 61.2,9.88 61.2,11.07 61.44,11.31 62.17,11.31 62.3,11.17 62.3,9.69 62.44,9.55 62.72,9.55 62.85,9.69 62.85,11.17 62.99,11.31 63.61,11.31 64.44,10.48 64.44,10.29 64.14,9.99 64.14,9.8 64.33,9.6 64.53,9.6 64.82,9.9 65.02,9.9 65.21,9.71 70.61,9.71 71,9.32 71.07,9.32 71.08,9.31 v1(71.48,9.31) 71.88,9.71 74.34,9.71 74.48,9.57 74.48,8.9 74.61,8.76 74.9,8.76 75.04,8.9 75.04,9.58 75.28,9.82 75.28,9.82 75.61,10.15 75.8,10.15 75.94,10.01 75.94,9.82 75.67,9.54 75.67,8.87 75.8,8.73 76.08,8.73 76.21,8.87 76.21,9.61 76.42,9.82 76.61,9.82 76.76,9.67 76.76,8.87 76.9,8.73 77.17,8.73 77.31,8.87 77.31,9.57 77.45,9.71 80.11,9.71 80.38,9.97 81.39,9.97 82,9.36 82.51,9.36 82.56,9.31 v1(82.96,9.31) ; U14.G27 71.06,34.96 71.06,34.45 71.37,34.14 71.37,33.32 72.59,32.11 73.3,32.11 74.02,31.38 v2(82.81,31.38)
  L3_INT_1 w0.107: v2(82.81,31.38) 83.63,31.38 83.78,31.23 83.78,29.41 83.94,29.25 85.35,29.25 85.51,29.41 85.51,29.63 85.35,29.78 84.47,29.78 84.31,29.94 84.31,30.16 84.47,30.32 85.35,30.32 85.51,30.47 85.51,30.69 85.35,30.85 84.47,30.85 84.31,31.01 84.31,31.23 84.47,31.38 85.8,31.38 86.84,30.35 88.19,30.35 88.96,29.58 88.96,29.04 89.08,28.91 89.66,28.91 89.79,28.79 89.79,28.61 89.66,28.49 89.08,28.49 88.96,28.36 88.96,28.18 89.08,28.06 89.66,28.06 89.79,27.93 89.79,27.76 89.66,27.63 89.08,27.63 88.96,27.51 88.96,27.33 89.08,27.21 89.66,27.21 89.79,27.08 89.79,26.9 89.66,26.78 89.08,26.78 88.96,26.65 88.96,26.39 88.24,25.67 88.24,25.1 89.23,24.11 89.23,23.93 89.1,23.8 89.1,23.62 89.23,23.5 89.4,23.5 89.53,23.63 89.71,23.63 89.84,23.5 89.84,23.32 89.7,23.19 89.7,23.02 89.83,22.89 90.01,22.89 90.14,23.02 90.31,23.02 90.44,22.9 90.44,22.72 90.31,22.59 90.31,22.41 90.43,22.29 90.61,22.29 90.74,22.42 90.92,22.42 91.04,22.29 91.04,22.12 90.91,21.99 90.91,21.81 91.04,21.69 91.21,21.69 91.34,21.82 91.52,21.82 91.65,21.69 91.65,21.51 91.52,21.38 91.52,21.21 91.64,21.08 91.82,21.08 91.95,21.21 92.12,21.21 92.25,21.09 92.25,20.91 92.12,20.78 92.12,20.6 92.24,20.48 92.42,20.48 92.55,20.61 92.73,20.61 93.37,19.97 93.37,16.23 92.62,15.48 92.62,14.85 92.63,14.84 92.96,14.51 92.96,13.07 93.76,12.26 93.76,11.57 93.64,11.44 93.37,11.44 93.24,11.32 93.24,11.14 93.37,11.01 93.64,11.01 93.76,10.89 93.76,10.71 93.64,10.59 93.37,10.59 93.24,10.46 93.24,10.29 93.37,10.16 93.64,10.16 93.76,10.04 93.76,9.41 93.87,9.31 v1(94.44,9.31)
  L4_INT_2 w0.107: v1(82.96,9.31) 84.02,9.31 84.4,8.92 84.72,8.92 84.94,9.15 84.94,9.51 85.64,10.2 87.29,10.2 88.1,9.39 89.18,9.39 89.48,9.69 90.6,9.69 90.82,9.47 90.82,9.18 91.08,8.92 91.4,8.92 91.66,9.18 92.69,9.18 92.79,9.29 92.79,10.35 92.9,10.46 93.16,10.46 93.26,10.35 93.26,9.41 93.37,9.31 v1(94.44,9.31)
D1_MA13: length 136.5
  TOP w0.137: R124.1 50.15,4.37 48.99,5.53 48.36,5.53 47.67,6.22 47.67,7.86 47.77,7.96 47.97,7.96 48.12,7.81 48.12,7.45 48.26,7.31 48.79,7.31 48.92,7.17 48.92,6.38 49.19,6.11 v1(49.32,6.11) ; U16.T8 83.72,6.07 83.72,5.68 83.72,5.38 v2(82.96,4.62) 82.67,4.62 81.34,3.29 74.08,3.29 73.94,3.42 73.94,4.6 73.8,4.74 73.53,4.74 73.39,4.6 73.39,3.45 73.23,3.29 72.89,3.29 72.57,3.61 72.57,4.93 72.28,5.22 U565.T8 71.85,5.68 71.85,5 69.08,2.23 60.94,2.23 59.84,3.32 59.84,5.15 v1(60.8,6.11) ; U14.AD27 56.58,34.73 56.58,34.45 56.05,33.92 55.69,33.92 55.44,33.67 55.44,30.27 64.82,20.89 87.84,20.89 88.49,20.24 90.33,20.24 90.33,20.19 v2(90.35,20.19)
  L3_INT_1 w0.107: v2(90.35,20.19) 90.35,19.78 90.42,19.71 90.42,14.19 91.24,13.38 91.24,11.78 91.84,11.18 91.84,6.69 92.43,6.11 v1(95.24,6.11)
  L4_INT_2 w0.107: v1(95.24,6.11) 95.53,5.82 95.53,5.19 95.28,4.95 83.29,4.95 v2(82.96,4.62)
  BOTTOM w0.137: v1(49.32,6.11) 49.47,5.96 49.47,5.84 50.06,5.25 51.39,5.25 53.16,3.47 53.18,3.47 53.31,3.34 55.38,3.34 55.96,2.75 57.45,2.75 59.11,4.41 59.3,4.41 59.57,4.14 59.77,4.14 59.96,4.33 59.96,4.53 59.69,4.8 59.69,5 v1(60.8,6.11)
D1_MACT_B: length 142
  TOP w0.137: v1(45.32,10.11) 45.09,10.11 44.69,10.51 44.32,10.51 44.12,10.71 44.12,11.1 43.91,11.31 43.56,11.31 42.46,12.41 42.46,12.57 42.44,12.58 42.44,14.45 41.01,15.88 R133.1 ; v1(91.24,10.11) 90.84,10.51 89.44,10.51 89.08,10.15 88.86,10.15 88.72,10.29 88.72,10.46 89,10.74 89.02,10.74 89.14,10.85 89.14,11.11 88.91,11.34 88.38,11.34 88.32,11.28 87.97,11.28 87.72,11.53 87.72,11.86 87.46,12.12 86.85,12.12 86.71,11.99 86.71,11.06 86.47,10.81 86.13,10.81 86,10.95 86,11.89 85.86,12.02 85.43,12.02 85.3,11.89 85.3,11.08 84.73,10.51 84.35,10.51 84.16,10.32 84.16,9.94 83.93,9.71 82.5,9.71 82.49,9.71 82.16,9.71 81.93,9.94 81.93,10.07 81.68,10.32 80.09,10.32 79.88,10.11 v1(79.76,10.11) ; v2(80.29,33.98) 75.01,33.98 74.95,33.92 73.99,33.92 73.31,34.6 U14.D28
  L3_INT_1 w0.107: v2(80.29,33.98) 81.31,33.98 81.44,34.1 81.44,34.48 81.59,34.64 83.16,34.64 83.31,34.79 83.31,35.01 83.16,35.17 81.59,35.17 81.44,35.33 81.44,35.55 81.59,35.7 83.16,35.7 83.31,35.86 83.31,36.08 83.16,36.24 81.59,36.24 81.44,36.39 81.44,36.65 81.2,36.88 77.25,36.88 77.01,36.63 77.01,34.43 77.11,34.32 77.97,34.32 79.42,32.88 79.42,32.53 79.26,32.37 78.29,32.37 78.14,32.21 78.14,31.99 78.29,31.84 79.26,31.84 79.42,31.68 79.42,31.46 79.26,31.3 78.29,31.3 78.14,31.15 78.14,30.93 78.29,30.77 79.26,30.77 79.42,30.61 79.42,30.39 79.26,30.24 78.29,30.24 78.14,30.08 78.14,29.86 78.29,29.7 79.26,29.7 79.42,29.55 79.42,29.45 87.57,21.3 87.57,15.58 88.24,14.91 88.24,13.77 88.86,13.16 88.86,12.75 89.26,12.35 89.26,11.55 89.5,11.31 89.83,11.31 89.83,11.3 90.04,11.09 90.04,10.74 90.27,10.51 90.84,10.51 v1(91.24,10.11) ; v1(56.8,10.11) 57.52,10.83 58.64,10.83 58.88,11.07 58.88,11.74 59.31,12.16 61.07,12.16 61.22,12.01 61.22,10.63 61.36,10.49 61.94,10.49 62.05,10.6 62.05,11.98 62.5,12.43 67.4,12.43 67.87,11.97 67.87,10.75 68.28,10.33 v1(68.28,10.11) 68.62,10.11 68.92,10.41 68.92,11.49 68.59,11.82 68.59,13.02 69.22,13.65 70.11,13.65 70.47,13.29 74.01,13.29 74.46,13.75 77.18,13.75 77.64,13.29 78.13,13.29 79.16,12.26 79.16,11.32 79.35,11.13 79.35,10.7 79.76,10.28 v1(79.76,10.11)
  L4_INT_2 w0.107: v1(45.32,10.11) 45.32,10.37 45.67,10.72 46.96,10.72 47.17,10.5 47.17,9.55 47.28,9.45 47.75,9.45 47.86,9.55 47.86,10.18 48.17,10.49 50.98,10.49 51.21,10.26 51.21,9.97 51.31,9.86 51.81,9.86 52.34,10.39 52.34,10.76 52.68,11.09 54.71,11.09 54.9,11.29 55.48,11.29 55.61,11.16 55.61,10.71 55.83,10.49 56.17,10.49 56.4,10.26 56.4,10.23 56.52,10.11 v1(56.8,10.11)
D1_MBA0: length 137.7
  TOP w0.137: U14.Y27 59.78,34.96 59.78,34.45 59.78,34.44 59.78,29.68 65.92,23.54 75.4,23.54 76.01,24.15 v2(80.76,24.15) ; v1(44.52,8.51) 44.12,8.91 43.55,8.91 42.58,9.87 41.7,9.87 41.45,10.12 41.45,10.48 41.2,10.72 40.85,10.72 40.65,10.92 40.65,12.26 40,12.91 39.56,12.91 R129.1
  L3_INT_1 w0.107: v1(78.96,8.51) 78.7,8.51 78.32,8.89 77.75,8.89 77.66,8.98 77.66,9.27 76.49,10.44 76.28,10.44 76.19,10.52 75.83,10.52 75.72,10.42 75.72,9.83 75.61,9.73 75.4,9.73 75.29,9.83 75.29,10.42 75.19,10.52 74.97,10.52 74.87,10.42 74.87,9.83 74.76,9.73 74.55,9.73 74.44,9.83 74.44,10.42 74.33,10.52 74.12,10.52 74.01,10.42 74.01,9.83 73.91,9.73 73.69,9.73 73.59,9.83 73.59,10.42 73.48,10.52 71.81,10.52 70.2,8.92 69.74,8.92 68.95,8.12 68.1,8.12 67.94,8.29 67.8,8.29 67.58,8.51 v1(67.48,8.51) 67.22,8.51 66.84,8.89 66.35,8.89 66.12,8.65 66.12,8.06 65.45,7.39 65.45,5.8 64.7,5.05 64.27,5.05 63.96,4.74 62.26,4.74 61.95,5.05 60.69,5.05 60.56,4.91 59.51,4.91 59.41,4.81 59.41,4.72 59.3,4.61 59.09,4.61 58.98,4.72 58.98,4.81 58.87,4.91 58.44,4.91 57.74,5.61 57.74,6.67 57.12,7.3 56.65,7.3 56.38,7.56 56.38,8.12 v1(56,8.51) ; v2(80.76,24.15) 80.73,24.12 79.45,24.12 79.11,24.45 79.11,26.52 79.01,26.62 78.54,26.62 78.44,26.52 78.44,24.87 77.06,23.49 77.06,22.79 77.17,22.69 82.22,22.69 85.68,19.22 85.68,15.87 85.49,15.68 85.49,14.66 85.92,14.23 85.92,12.52 87.43,11.01 87.43,10.14 87.72,9.85 87.72,9.82 89.43,8.1 89.89,8.1 90.29,8.51 v1(90.44,8.51)
  L4_INT_2 w0.107: v1(44.52,8.51) 44.22,8.51 44.11,8.4 44.11,8.19 44.19,8.11 45.7,8.11 46.66,7.15 46.66,6.52 47.12,6.06 48.73,6.06 49.19,6.52 51.64,6.52 52.12,6.04 53.3,6.04 53.54,6.28 53.54,7.23 54.23,7.92 54.25,7.92 54.7,8.38 55.04,8.38 55.04,8.38 55.88,8.38 v1(56,8.51) ; v1(78.96,8.51) 78.96,8.37 79.35,7.98 79.35,7.51 79.58,7.29 80.2,7.29 80.31,7.4 80.31,7.87 80.42,7.98 80.63,7.98 80.74,7.87 80.74,7.4 80.84,7.29 81.13,7.29 81.97,8.12 83.26,8.12 83.77,7.61 85.11,7.61 85.97,8.47 86.44,8.47 86.54,8.37 86.54,8.24 86.65,8.13 86.86,8.13 86.97,8.24 86.97,8.37 87.08,8.47 87.29,8.47 87.4,8.37 87.4,8.24 87.5,8.13 87.72,8.13 87.82,8.24 87.82,8.37 87.93,8.47 88.67,8.47 89.11,8.03 89.96,8.03 v1(90.44,8.51)
D1_MBA1: length 134.5
  TOP w0.137: v1(95.24,8.51) 94.84,8.11 94.28,8.11 93.84,7.67 92.64,7.67 92.18,8.13 92.18,8.32 92.34,8.48 92.34,8.67 92.14,8.86 91.95,8.86 91.8,8.71 91.6,8.71 91.41,8.91 91.32,8.91 91.32,8.91 89.48,8.91 89.3,9.09 88.93,9.09 88.79,8.95 88.79,8.09 88.65,7.95 88.38,7.95 88.24,8.09 88.24,8.95 88.11,9.09 87.83,9.09 87.69,8.95 87.69,8.09 87.56,7.95 87.28,7.95 87.15,8.09 87.15,8.95 87.01,9.09 86.73,9.09 86.6,8.95 86.6,8.58 86.46,8.44 86.19,8.44 86.05,8.58 86.05,8.95 85.91,9.09 84.96,9.09 84.78,8.91 84.16,8.91 v1(83.76,8.51) ; U14.W28 61.02,33.76 61.12,33.67 61.12,29.6 66.26,24.45 75.04,24.45 75.77,25.18 82.06,25.18 82.81,24.43 92.45,24.43 92.61,24.59 92.61,25.14 92.77,25.3 93,25.3 93.16,25.14 93.16,24.59 93.32,24.43 94.13,24.43 94.4,24.7 v2(94.95,24.7)
  L3_INT_1 w0.107: v2(94.95,24.7) 94.95,24.41 98.84,20.52 98.84,11.46 96.28,8.9 95.63,8.9 v1(95.24,8.51)
  L4_INT_2 w0.107: v1(60.8,8.51) 61.18,8.89 62.12,8.89 62.64,8.37 62.64,8.16 63.05,7.75 63.05,6.91 63.22,6.75 64.84,6.75 64.94,6.85 64.94,7.85 65.08,7.99 65.08,8.97 65.25,9.13 66.01,9.13 66.25,8.89 71.9,8.89 v1(72.28,8.51) 72.82,8.51 74.39,6.94 74.72,6.94 74.82,7.04 74.82,7.7 74.93,7.8 75.14,7.8 75.25,7.7 75.25,7.04 75.36,6.94 76.33,6.94 77.52,8.13 77.52,8.41 78,8.89 79.12,8.89 79.38,8.63 79.38,8.33 79.59,8.12 80,8.12 80.37,8.5 81.76,8.5 81.79,8.53 82.44,8.53 82.8,8.89 83.38,8.89 v1(83.76,8.51)
  BOTTOM w0.137: R128.1 47.19,5.27 47.19,6.54 47.32,6.68 47.46,6.68 47.6,6.81 47.6,7.09 47.46,7.22 47.32,7.22 47.19,7.36 47.19,7.73 47.56,8.11 48.69,8.11 48.92,8.11 v1(49.32,8.51) 49.75,8.08 49.75,7.91 49.91,7.75 51.8,7.75 52.89,6.66 52.89,6.31 53.28,5.92 53.32,5.92 53.53,5.71 54.63,5.71 54.85,5.93 56,5.93 56.09,6.02 56.44,6.02 56.53,6.1 56.53,6.59 56.41,6.72 56.4,6.72 56.4,7.87 56.64,8.11 56.97,8.11 57.05,8.02 57.82,8.02 58.31,8.51 v1(60.8,8.51)
